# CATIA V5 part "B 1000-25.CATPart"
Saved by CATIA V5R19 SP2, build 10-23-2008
Part number: B 1000-25
Bounding box of the stored display mesh (mm): x -24.865 to 24.865, y -24.997 to 24.997, z 0 to 145
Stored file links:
  C:\Users\Bora\Desktop\3D Katı model\B serisi\B 1000\B 1000-25.CATPart
  C:\Program Files\Dassault Systemes\B19\intel_a\reffiles\standard\MetricThickPitch.txt
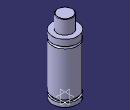
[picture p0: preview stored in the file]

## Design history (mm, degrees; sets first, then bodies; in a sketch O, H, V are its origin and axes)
Body1 (main body)
  Sketch1 on yz-plane, origin (0, 0, 0), H (0, 1, 0), V (0, 0, 1)
    point P1 (25, 104.5)
    point P2 (25, 100.5)
    point P3 (25, 104.5)
    point P6 (25, 100.5)
    point P9 (15, 144)
    point P11 (15, 144)
    arc A1 centre (25, 102.5) radius 2 from (25, 104.5) to (25, 100.5) ccw
    line L1 (25, 104.5) -> (25, 117)
    line L2 (25, 13) -> (25, 100.5)
    line L3 (21.5, 13) -> (21.5, 8)
    arc A2 centre (14, 144) radius 1 from (15, 144) to (14, 145) ccw
    line L4 (15, 144) -> (15, 117)
    line L5 (25, 0) -> (25, 8)
    line L6 (14, 145) -> (0, 145)
    point P15 (0, 145)
    line L7 (15, 117) -> (25, 117)
    line L8 (0, 0) -> (25, 0)
    line L9 (21.5, 13) -> (25, 13)
    line L10 (21.5, 8) -> (25, 8)
    tangency: L6 A2
    coincidence: P15 V, P1 P3, P2 P6, P9 P11
    horizontal: L7 H, L8 H, L9 H, L10 H
  Shaft1: profile Sketch1, axis Sketch1.V, angle 360
  Sketch2 on face of Shaft1 from Sketch1.L8, origin (0, 0, 0), H (1, 0, 0), V (0, -1, 0)
    point P1 (10, 0)
    distance P1 V = 10
  Hole1: placed by Sketch2, at (10, 0, 0) direction (0, 0, 1), diameter 6.647, depth 13, threaded "M8", thread diameter 8, thread depth 13, pitch 1.25
  CircPattern1: of Hole1, instances 2, angular step 180, axis from xy-plane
